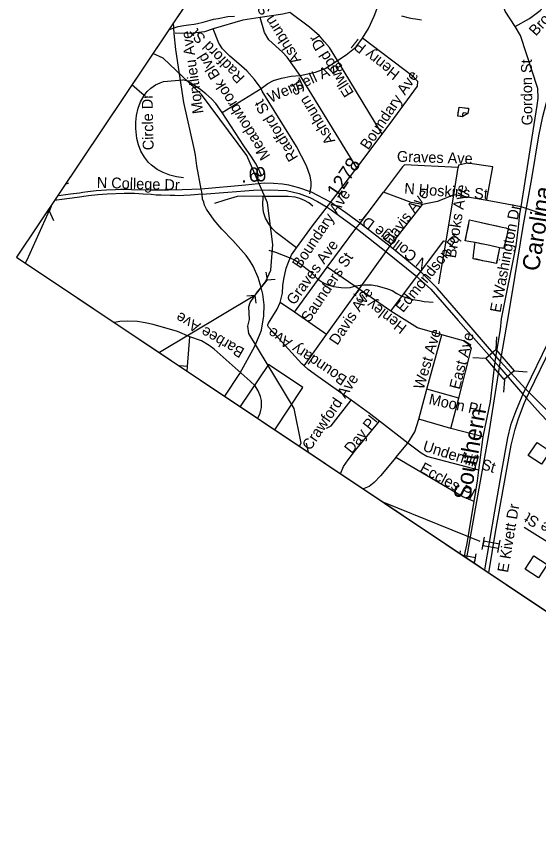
# Model space of a CAD drawing. Extents: x 1715610 to 1720914, y 798298 to 802505.
# Drawn here: x 1715610 to 1715709.6, y 799408.2 to 799566.4 of the extents above; entities that cross this region are included whole.
import ezdxf

# ---------------------------------------------------------------- set-up
doc = ezdxf.new("R2010")
doc.units = 0
doc.layers.add('Default', color=7, linetype='Continuous')
doc.layers.add('Prop DSN Text', color=7, linetype='Continuous')

msp = doc.modelspace()

# ---------------------------------------------------------------- linework, layer by layer
at = {"layer": 'Default'}
for p, q in [((1715825.88, 799842.99), (1715610.03, 799520.5)), ((1715825.88, 799842.99), (1715610.03, 799520.5)), ((1715679.77, 799543.94), (1715671.24, 799558)), ((1715674.94, 799537.52), (1715664.11, 799555.19)), ((1715649.23, 799548.1), (1715656.69, 799552.66)), ((1715674.94, 799537.52), (1715679.77, 799543.94)), ((1715669.54, 799530.39), (1715674.94, 799537.52)), ((1715693.41, 799532.38), (1715694.26, 799537.57)), ((1715619.91, 799534.58), (1715619.28, 799534.32)), ((1715675.37, 799526.71), (1715680, 799532.86)), ((1715691.98, 799523.51), (1715693.41, 799532.38)), ((1715699.76, 799531.32), (1715693.41, 799532.38)), ((1715616.28, 799529.27), (1715616.8, 799530.61)), ((1715681.11, 799522.4), (1715687.43, 799530.53)), ((1715706.25, 799530.08), (1715699.76, 799531.32)), ((1715615.76, 799529.06), (1715616.28, 799529.27)), ((1715617.16, 799527.43), (1715616.28, 799529.27)), ((1715669.3, 799518.55), (1715674.71, 799525.96)), ((1715674.71, 799525.96), (1715675.37, 799526.71)), ((1715690.56, 799515.41), (1715691.98, 799523.51)), ((1715675.35, 799514.34), (1715680.52, 799521.57)), ((1715680.52, 799521.57), (1715681.11, 799522.4)), ((1715610.03, 799520.5), (1715972.32, 799278.02)), ((1715610.03, 799520.5), (1715972.32, 799278.02)), ((1715663.02, 799509.94), (1715669.3, 799518.55)), ((1715675.35, 799514.34), (1715669.3, 799518.55)), ((1715657.59, 799517.6), (1715657.8, 799516.08)), ((1715659.34, 799516.21), (1715657.8, 799516.08)), ((1715681.41, 799510.18), (1715686.34, 799516.72)), ((1715686.34, 799516.72), (1715686.89, 799517.45)), ((1715655.51, 799513.22), (1715657.8, 799516.08)), ((1715653.97, 799513.09), (1715655.51, 799513.22)), ((1715655.72, 799511.69), (1715655.51, 799513.22)), ((1715669.14, 799505.69), (1715675.35, 799514.34)), ((1715681.41, 799510.18), (1715675.35, 799514.34)), ((1715655.17, 799512.96), (1715637.31, 799502.25)), ((1715663.02, 799509.94), (1715660.33, 799511.83)), ((1715669.14, 799505.69), (1715663.02, 799509.94)), ((1715642.65, 799499.58), (1715643.1, 799505.24)), ((1715664.87, 799499.74), (1715669.14, 799505.69)), ((1715688.3, 799495.29), (1715691.12, 799505.63)), ((1715701.58, 799505.27), (1715701.41, 799502.82)), ((1715697.05, 799501.33), (1715699.51, 799501.16)), ((1715701.34, 799500.56), (1715701.53, 799501.73)), ((1715642.65, 799499.58), (1715641.11, 799499.7)), ((1715704.94, 799498.74), (1715707.4, 799498.57)), ((1715703.08, 799497.13), (1715702.91, 799494.67)), ((1715686.73, 799489.53), (1715688.3, 799495.29)), ((1715694.36, 799493.58), (1715688.3, 799495.29)), ((1715692.88, 799487.76), (1715694.36, 799493.58)), ((1715652.69, 799491.95), (1715659.29, 799487.53)), ((1715692.88, 799487.76), (1715686.73, 799489.53)), ((1715684.67, 799484.98), (1715679.23, 799489.19)), ((1715699.01, 799486.16), (1715692.88, 799487.76)), ((1715698.23, 799479.78), (1715699.01, 799486.16)), ((1715682.37, 799482.24), (1715684.67, 799484.98)), ((1715698.43, 799466.16), (1715680.11, 799473.6)), ((1715716.53, 799462.76), (1715706.87, 799468.84)), ((1715698.84, 799464.66), (1715699.28, 799467.02)), ((1715701.82, 799464.1), (1715702.26, 799466.46)), ((1715694.64, 799463.87), (1715694.73, 799464.38)), ((1715695.23, 799463.48), (1715696.91, 799462.35)), ((1715697.38, 799462.04), (1715697.72, 799463.83))]:
    msp.add_line(p, q, dxfattribs=at)
for points in [[(1715675.99, 799562.27), (1715677.14, 799564.16), (1715678.24, 799566.46), (1715678.75, 799567.81), (1715680.1, 799572.11), (1715690.96, 799586.76), (1715694.6, 799591.45)], [(1715733.84, 799587.8), (1715729.32, 799582.48), (1715721.94, 799570.86), (1715717.48, 799562.96), (1715715.52, 799559.19), (1715714.52, 799556.87), (1715713.46, 799552.5), (1715713.22, 799550.57), (1715713.19, 799548.01), (1715714.27, 799537.69), (1715715.14, 799530.33), (1715715.35, 799527.47), (1715715.67, 799525.51), (1715715.93, 799521.37), (1715715.92, 799518.22), (1715715.57, 799515.43), (1715714.81, 799512.55), (1715713.86, 799509.92), (1715711.38, 799504.12), (1715707.11, 799495.36)], [(1715707.79, 799494.65), (1715712.08, 799503.42), (1715714.29, 799508.12), (1715714.94, 799509.43), (1715715.94, 799512.15), (1715716.75, 799515.1), (1715716.87, 799516.33), (1715716.97, 799520.41), (1715716.62, 799524.27), (1715716.37, 799527.29), (1715715.69, 799533.91), (1715714.76, 799541.07), (1715714.06, 799547.26), (1715713.99, 799549.57), (1715714.18, 799551.78), (1715714.68, 799554.51), (1715715.42, 799556.88), (1715716.77, 799559.87), (1715717.47, 799561.27), (1715721.86, 799569.03), (1715723.8, 799572.16), (1715729.96, 799581.74), (1715731.53, 799584.15), (1715733.84, 799587.8)], [(1715705.11, 799564.49), (1715703.24, 799567.47), (1715702.58, 799569.36), (1715701.97, 799572.43), (1715701.61, 799575.85), (1715701.31, 799577.72), (1715700.88, 799579.57), (1715700.38, 799581.24)], [(1715705.11, 799564.49), (1715707.86, 799566.04), (1715709.89, 799567.57), (1715711.49, 799569.38), (1715713.85, 799572.49)], [(1715671.24, 799558), (1715669.69, 799560.48), (1715668.78, 799561.62), (1715667.79, 799562.71), (1715665.88, 799564.42), (1715662.13, 799567.21), (1715660.8, 799566.85), (1715656.46, 799566.23)], [(1715695.88, 799463.04), (1715697.55, 799472.42), (1715700.02, 799486.17), (1715702.12, 799499.45), (1715702.23, 799499.92), (1715702.33, 799500.54), (1715703.93, 799509.65), (1715705.09, 799516.61), (1715706.64, 799526.36), (1715708.3, 799535.52), (1715709.62, 799543.64), (1715710.39, 799547.31), (1715711.03, 799549.75), (1715712.25, 799554.12), (1715713.05, 799556.56), (1715714.04, 799559.18), (1715715.27, 799562.03), (1715716.13, 799563.82), (1715717.08, 799565.74), (1715718.15, 799567.91)], [(1715639.1, 799563.93), (1715639.2, 799563.97), (1715639.9, 799564.23), (1715640.82, 799564.5), (1715641.91, 799564.7), (1715642.8, 799564.83), (1715643.9, 799564.98), (1715644.54, 799565.07), (1715645.61, 799565.33), (1715646.98, 799565.72), (1715647.57, 799565.89), (1715648.48, 799566.06), (1715650.3, 799566.4), (1715651.59, 799566.52)], [(1715645.24, 799533.43), (1715644.44, 799537.93), (1715644.17, 799539.98), (1715643.91, 799541.22), (1715641.95, 799550.03), (1715640.43, 799560.15), (1715640.06, 799563.17), (1715639.98, 799565.25)], [(1715656.46, 799566.23), (1715653.17, 799565.72), (1715647.53, 799564.06)], [(1715664.11, 799555.19), (1715661.61, 799558.67), (1715660.74, 799559.6), (1715658.15, 799561.98), (1715657.31, 799563.4), (1715656.46, 799566.23)], [(1715683.45, 799566.57), (1715684.91, 799566.16), (1715685.56, 799566.03), (1715686.14, 799565.95), (1715687.26, 799565.82)], [(1715647.53, 799564.06), (1715645.87, 799563.52), (1715643.12, 799563.15), (1715640.28, 799563.24)], [(1715656.69, 799552.66), (1715655.41, 799554.38), (1715653.96, 799556.08), (1715652.44, 799557.38), (1715650.69, 799558.86), (1715649.33, 799560.26), (1715648.59, 799561.32), (1715647.53, 799564.06)], [(1715706.25, 799530.08), (1715709.35, 799549.45), (1715709.54, 799550.82), (1715709.44, 799552.7), (1715706.14, 799562.83), (1715705.11, 799564.49)], [(1715671.24, 799558), (1715672.87, 799559.12), (1715674.78, 799560.62), (1715675.99, 799562.27)], [(1715679.77, 799543.94), (1715682.01, 799546.94), (1715686.48, 799553.14), (1715686.56, 799554.01), (1715685.73, 799554.92), (1715675.99, 799562.27)], [(1715663.99, 799484.39), (1715664.31, 799484.95), (1715662.95, 799491.6), (1715654.31, 799505.87), (1715654.11, 799507.31), (1715654.45, 799508.58), (1715654.35, 799510.97), (1715654.56, 799511.8), (1715656.01, 799513.83), (1715656.65, 799514.66), (1715657.49, 799515.74), (1715658.5, 799518.01), (1715658.89, 799522.92), (1715657.9, 799530.83), (1715653.95, 799539.89), (1715645.28, 799551.53), (1715637.96, 799558.5), (1715636.03, 799559.34)], [(1715664.11, 799555.19), (1715667.07, 799555.78), (1715668.87, 799556.5), (1715671.24, 799558)], [(1715634.34, 799551.33), (1715634.96, 799552.11), (1715635.66, 799552.77), (1715636.55, 799553.37), (1715637.4, 799553.79), (1715638.08, 799554.02), (1715641.71, 799554.33)], [(1715649.23, 799548.1), (1715648.04, 799549.82), (1715647.21, 799550.7), (1715646.15, 799551.68), (1715644.94, 799552.61), (1715642.61, 799554.1), (1715641.71, 799554.33)], [(1715656.69, 799552.66), (1715657.95, 799553.61), (1715659.05, 799554.19), (1715660.53, 799554.68), (1715662.4, 799555.01), (1715664.11, 799555.19)], [(1715634.34, 799551.33), (1715632.04, 799553.38)], [(1715665.98, 799532.56), (1715666.21, 799533.95), (1715666.21, 799534.87), (1715666.01, 799535.94), (1715665.36, 799537.91), (1715663.41, 799541.63), (1715656.88, 799552.19), (1715656.69, 799552.66)], [(1715641.89, 799535.63), (1715640.54, 799535.8), (1715639.25, 799536.13), (1715638.02, 799536.61), (1715636.85, 799537.24), (1715635.76, 799538.01), (1715635.19, 799538.58), (1715634.4, 799539.59), (1715633.76, 799540.71), (1715633.28, 799541.9), (1715632.97, 799543.15), (1715632.76, 799545.01), (1715632.75, 799546.28), (1715632.89, 799547.54), (1715633.23, 799548.95), (1715633.69, 799550.13), (1715634.34, 799551.33)], [(1715656.88, 799536), (1715656.61, 799536.3), (1715656.26, 799537.22), (1715655.63, 799538.43), (1715654.86, 799539.64), (1715653.37, 799541.71), (1715649.23, 799548.1)], [(1715694.46, 799549.14), (1715695.05, 799549.06), (1715695.62, 799548.98), (1715695.91, 799548.95), (1715696.2, 799548.91), (1715696.2, 799548.59), (1715696.11, 799547.92), (1715695.74, 799548), (1715695.2, 799548.06), (1715695.11, 799547.7), (1715695.01, 799547.24), (1715694.75, 799547.32), (1715694.17, 799547.4), (1715694.27, 799548.01), (1715694.36, 799548.69), (1715694.46, 799549.14)], [(1715694.46, 799549.14), (1715695.05, 799549.06), (1715695.91, 799548.95), (1715696.2, 799548.91), (1715696.2, 799548.59), (1715696.11, 799547.92), (1715695.01, 799547.24), (1715694.17, 799547.4), (1715694.36, 799548.69), (1715694.46, 799549.14)], [(1715699.76, 799531.32), (1715699.75, 799531.51), (1715700.88, 799537.71), (1715696.05, 799538.4), (1715694.34, 799538.05), (1715694.26, 799537.57)], [(1715694.26, 799537.57), (1715684.01, 799538.1), (1715683.96, 799538.05), (1715683.66, 799537.72), (1715680, 799532.86)], [(1715702.33, 799500.54), (1715701.45, 799501.54), (1715695.13, 799508.88), (1715690.24, 799514.53), (1715686.93, 799517.84), (1715681.51, 799522.29), (1715675.67, 799526.85), (1715672.8, 799528.91), (1715669.92, 799530.97), (1715666.31, 799532.86), (1715663.89, 799533.7), (1715661.96, 799534.23), (1715660.74, 799534.44), (1715659.02, 799534.56), (1715657.34, 799534.59), (1715653.72, 799534.23), (1715645.24, 799533.43)], [(1715645.41, 799532.5), (1715643.18, 799532.33), (1715641.94, 799532.24), (1715641, 799532.21), (1715640.2, 799532.22), (1715639.31, 799532.25), (1715637.58, 799532.3), (1715636.64, 799532.34), (1715635.7, 799532.41), (1715634.2, 799532.53), (1715632.51, 799532.61), (1715631.41, 799532.64), (1715630.54, 799532.66), (1715627.3, 799532.48), (1715625.52, 799532.36), (1715623.77, 799532.17), (1715621.6, 799531.88), (1715618.69, 799531.51), (1715617.68, 799531.38), (1715617.29, 799531.35)], [(1715645.24, 799533.43), (1715641.63, 799533.33), (1715638.99, 799533.27), (1715635.62, 799533.28), (1715631.95, 799533.34), (1715631.4, 799533.38), (1715630.64, 799533.39), (1715629.87, 799533.39), (1715628.89, 799533.36), (1715627.18, 799533.28), (1715625.21, 799533.11), (1715623.63, 799532.93), (1715622.69, 799532.8), (1715622.03, 799532.72), (1715620.31, 799532.5), (1715619.33, 799532.36), (1715618.56, 799532.27), (1715617.87, 799532.21)], [(1715645.41, 799532.5), (1715645.34, 799532.93), (1715645.24, 799533.43)], [(1715645.41, 799532.5), (1715655.19, 799533.25), (1715658.26, 799533.31), (1715661.54, 799533.2), (1715663.9, 799532.65), (1715665.95, 799531.89), (1715667.43, 799531.11), (1715669.27, 799529.99), (1715670.06, 799529.48), (1715674.5, 799526.24), (1715675.92, 799525.1), (1715680.75, 799521.32), (1715686.05, 799517.01), (1715689.05, 799514.36), (1715694.25, 799508.38), (1715702.12, 799499.45)], [(1715649.76, 799493.91), (1715652.6, 799498.27), (1715655.46, 799503.46), (1715656.38, 799505.55), (1715656.72, 799506.53), (1715657.22, 799509.26), (1715657.28, 799511.37), (1715656.99, 799513.44), (1715656.65, 799514.66), (1715656.13, 799516.58), (1715655.13, 799518.76), (1715654.46, 799519.92), (1715653.8, 799520.76), (1715651.28, 799523.64), (1715649.18, 799525.8), (1715647.7, 799527.52), (1715646.27, 799529.64), (1715645.9, 799530.41), (1715645.74, 799530.99), (1715645.52, 799531.54), (1715645.41, 799532.5)], [(1715657.06, 799532.07), (1715653.58, 799532.1), (1715652.11, 799532.04), (1715649.75, 799531.37), (1715647.75, 799530.7)], [(1715663.45, 799522.25), (1715659.57, 799525.16), (1715658.8, 799525.93), (1715658.12, 799526.81), (1715657.53, 799527.89), (1715657.1, 799529.06), (1715656.99, 799530.49), (1715657.06, 799532.07)], [(1715666.52, 799530.23), (1715665.77, 799530.83), (1715664.95, 799531.32), (1715664.07, 799531.69), (1715663.15, 799531.93), (1715661.86, 799532.04), (1715657.06, 799532.07)], [(1715687.43, 799530.53), (1715685.29, 799530.9), (1715680, 799532.86)], [(1715693.41, 799532.38), (1715690.31, 799531.1), (1715687.43, 799530.53)], [(1715663.45, 799522.25), (1715666.49, 799526.45), (1715669.54, 799530.39)], [(1715611.72, 799519.37), (1715612.07, 799519.97), (1715616.03, 799528.89), (1715616.61, 799530.33)], [(1715701.53, 799501.73), (1715702.32, 799506.67), (1715702.53, 799508.72), (1715705.31, 799522.63), (1715705.79, 799526.19), (1715706.03, 799528.74), (1715706.25, 799530.08)], [(1715715.5, 799527.18), (1715710.88, 799528.57), (1715706.25, 799530.08)], [(1715697.49, 799523.26), (1715696.32, 799523.48), (1715695.58, 799523.62), (1715695.69, 799524.01), (1715695.93, 799525.06), (1715696.15, 799526.07), (1715696.29, 799526.82), (1715696.38, 799527.34), (1715696.39, 799527.59), (1715697.56, 799527.37), (1715698.65, 799527.11), (1715699.75, 799526.87), (1715700.7, 799526.65), (1715701.62, 799526.44), (1715702.63, 799526.23), (1715703.35, 799526.05), (1715703.79, 799525.91), (1715703.75, 799525.62), (1715703.6, 799524.94), (1715703.4, 799524.12), (1715703.24, 799523.34), (1715703.1, 799522.74), (1715702.93, 799522.12), (1715702.71, 799522.17), (1715702.13, 799522.25)], [(1715697.49, 799523.26), (1715696.32, 799523.48), (1715695.58, 799523.62), (1715696.39, 799527.59), (1715697.56, 799527.37), (1715702.63, 799526.23), (1715703.35, 799526.05), (1715703.79, 799525.91), (1715703.75, 799525.62), (1715703.6, 799524.94), (1715703.24, 799523.34), (1715703.1, 799522.74), (1715702.93, 799522.12), (1715702.13, 799522.25)], [(1715686.89, 799517.45), (1715691.5, 799523.57), (1715691.98, 799523.51)], [(1715702.13, 799522.25), (1715702.06, 799521.93), (1715701.94, 799521.28), (1715701.82, 799520.72), (1715701.72, 799520.11), (1715701.56, 799519.58), (1715701.56, 799519.26), (1715700.68, 799519.44), (1715699.73, 799519.67), (1715698.93, 799519.8), (1715698.24, 799519.95), (1715697.75, 799520.08), (1715697.4, 799520.11), (1715697.13, 799520.18), (1715697.26, 799521.52), (1715697.35, 799522.35), (1715697.44, 799523.03), (1715697.49, 799523.26)], [(1715702.13, 799522.25), (1715701.56, 799519.26), (1715697.4, 799520.11), (1715697.13, 799520.18), (1715697.26, 799521.52), (1715697.35, 799522.35), (1715697.44, 799523.03), (1715697.49, 799523.26)], [(1715697.49, 799523.26), (1715697.51, 799523.35), (1715698.55, 799523.11), (1715699.36, 799522.98), (1715700.27, 799522.78), (1715701.09, 799522.59), (1715701.65, 799522.47), (1715702.14, 799522.35), (1715702.13, 799522.25)], [(1715697.49, 799523.26), (1715697.51, 799523.35), (1715699.36, 799522.98), (1715700.27, 799522.78), (1715701.65, 799522.47), (1715702.14, 799522.35), (1715702.13, 799522.25)], [(1715658.13, 799521.79), (1715659.42, 799521.44), (1715662.36, 799520.27), (1715663.18, 799519.93), (1715664.05, 799519.28), (1715666.04, 799517.71), (1715666.68, 799517.11), (1715667.38, 799516.43), (1715667.89, 799516.03), (1715668.43, 799515.65), (1715669.37, 799515.18), (1715670.46, 799514.85), (1715671.93, 799514.69), (1715672.73, 799514.62), (1715673.68, 799514.7), (1715674.76, 799514.97), (1715675.54, 799515.12), (1715676.32, 799515.17), (1715677.03, 799515.21), (1715677.72, 799515.21), (1715678.83, 799514.98), (1715680.77, 799514.44), (1715681.68, 799514.14), (1715682.57, 799513.53), (1715683.51, 799513.05), (1715685.6, 799512.41), (1715686.87, 799512.18), (1715687.77, 799512.03), (1715689.52, 799511.89)], [(1715660.33, 799511.83), (1715660.73, 799513.63), (1715660.82, 799515.05), (1715660.99, 799516.26), (1715661.48, 799518.35), (1715661.88, 799519.51), (1715662.49, 799520.91), (1715663.45, 799522.25)], [(1715664.87, 799499.74), (1715664.44, 799500.12), (1715658.1, 799507.1), (1715657.95, 799507.35), (1715657.93, 799507.58), (1715658.07, 799507.9), (1715659.74, 799510.55), (1715660.33, 799511.83)], [(1715691.12, 799505.63), (1715686.5, 799506.99), (1715681.41, 799510.18)], [(1715643.1, 799505.24), (1715640.71, 799506.25), (1715636.05, 799507.61), (1715634.57, 799507.96), (1715633.08, 799508.16), (1715631.26, 799508.24), (1715629.75, 799508.16), (1715628.7, 799508)], [(1715652.31, 799498.85), (1715647.74, 799502.88), (1715646.79, 799503.61), (1715645.32, 799504.5), (1715643.1, 799505.24)], [(1715694.36, 799493.58), (1715696.77, 799503.09), (1715696.24, 799503.77), (1715695.3, 799504.52), (1715691.12, 799505.63)], [(1715699.01, 799486.16), (1715700.4, 799492.94), (1715701.34, 799500.56)], [(1715707.11, 799495.36), (1715702.33, 799500.54)], [(1715642.58, 799498.72), (1715642.65, 799499.58)], [(1715656.04, 799489.71), (1715656.2, 799489.98), (1715656.49, 799490.68), (1715656.64, 799491.24), (1715656.74, 799491.8), (1715656.76, 799492.56), (1715656.73, 799493.13), (1715656.56, 799493.88), (1715656.14, 799494.93), (1715655.51, 799495.89), (1715654.6, 799496.79), (1715652.31, 799498.85)], [(1715659.29, 799487.53), (1715664.66, 799495.56), (1715658.06, 799499.98), (1715652.69, 799491.95)], [(1715673.85, 799493.15), (1715667.51, 799497.68), (1715665.64, 799499.05), (1715664.87, 799499.74)], [(1715702.12, 799499.45), (1715706.62, 799494.29)], [(1715706.62, 799494.29), (1715705.96, 799492.76), (1715705.18, 799490.96), (1715704.24, 799488.37), (1715703.64, 799485.99), (1715702.44, 799479.27), (1715701.2, 799472), (1715699.3, 799460.75)], [(1715707.11, 799495.36), (1715706.81, 799494.74), (1715706.62, 799494.29)], [(1715706.62, 799494.29), (1715706.88, 799493.99), (1715707.29, 799493.53)], [(1715707.79, 799494.65), (1715707.38, 799495.08), (1715707.11, 799495.36)], [(1715707.29, 799493.53), (1715707.65, 799494.37), (1715707.79, 799494.65)], [(1715760.72, 799449.69), (1715760.58, 799449.8), (1715753.26, 799455.6), (1715746.04, 799461.08), (1715738.6, 799466.72), (1715734.62, 799469.89), (1715730.9, 799473.01), (1715728.54, 799475.23), (1715727.1, 799476.64), (1715723.6, 799480.04), (1715719.83, 799483.39), (1715716.72, 799486.21), (1715714.47, 799488.13), (1715712.62, 799489.82), (1715710.38, 799492.02), (1715707.79, 799494.65)], [(1715669.12, 799487.83), (1715670.02, 799488.25), (1715673.85, 799493.15)], [(1715679.23, 799489.19), (1715677.36, 799490.64), (1715673.85, 799493.15)], [(1715700.09, 799460.22), (1715701.37, 799467.95), (1715704.12, 799483.17), (1715704.38, 799484.59), (1715705.11, 799487.61), (1715705.76, 799489.64), (1715706.86, 799492.55), (1715707.29, 799493.53)], [(1715707.29, 799493.53), (1715709.98, 799490.54), (1715712.78, 799487.65), (1715719.02, 799482.24), (1715726.03, 799475.8), (1715727.72, 799474.21), (1715734.06, 799468.59), (1715743.7, 799461.13), (1715748.49, 799457.6), (1715753.92, 799453.3), (1715759.88, 799448.58)], [(1715684.67, 799484.98), (1715685.97, 799487.1), (1715686.73, 799489.53)], [(1715671.84, 799479.13), (1715672.39, 799480.51), (1715673.25, 799481.78), (1715674.65, 799483.64), (1715679.23, 799489.19)], [(1715665.26, 799484.94), (1715665.67, 799483.26)], [(1715698.23, 799479.78), (1715688.31, 799482.44), (1715687.17, 799483.03), (1715684.67, 799484.98)], [(1715682.37, 799482.24), (1715679.42, 799478.75), (1715678.26, 799477.46), (1715677.28, 799476.71), (1715676.33, 799476.28), (1715676.17, 799476.23)], [(1715697.29, 799473.84), (1715695.12, 799474.71), (1715682.37, 799482.24)], [(1715697.29, 799473.84), (1715697.95, 799477.76), (1715698.23, 799479.78)], [(1715695.47, 799463.31), (1715695.65, 799464.38), (1715695.88, 799465.47), (1715697.29, 799473.84)], [(1715696.91, 799462.35), (1715697.42, 799462.26), (1715697.57, 799463.04), (1715695.23, 799463.48)]]:
    msp.add_lwpolyline(points, dxfattribs=at)
for points in [[(1715701.41, 799502.82), (1715704.95, 799498.75), (1715703.05, 799497.1), (1715699.51, 799501.16)], [(1715707.61, 799482.6), (1715709.3, 799485.11), (1715711.81, 799483.43), (1715710.13, 799480.92)], [(1715702.11, 799465.67), (1715699.13, 799466.23), (1715698.98, 799465.45), (1715701.97, 799464.89)], [(1715707.04, 799460.93), (1715708.72, 799463.45), (1715711.23, 799461.76), (1715709.55, 799459.25)]]:
    msp.add_lwpolyline(points, close=True, dxfattribs=at)
at = {"layer": 'Prop DSN Text'}
msp.add_lwpolyline([(1715972.32, 799278.02), (1716250.51, 799693.66), (1715888.23, 799936.14), (1715610.03, 799520.5)], close=True, dxfattribs=at)

# ---------------------------------------------------------------- texts
at = {"layer": 'Default'}
for s, height, rotation, p in [('Brockett Ave', 2.0663, 47.7257, (1715709.07, 799562.58)), ('Ashburn St', 2.066, 122.0781, (1715664.39, 799558.11)), ('Radford St', 2.066, 134.5095, (1715653.68, 799554.88)), ('Montlieu Ave', 2.0663, 98.1362, (1715645.67, 799548)), ('Ellwood Dr', 2.066, 121.8391, (1715674.43, 799551.85)), ('Henry Pl', 2.066, 141.6587, (1715683.27, 799555.74)), ('Meadowbrook Blvd', 2.0663, 121.7735, (1715658.48, 799539.78)), ('Wendell Ave', 2.0663, 24.6555, (1715658.49, 799549.91)), ('Gordon St', 2.066, 90.6546, (1715708.44, 799545.65)), ('Boundary Ave', 2.0663, 56.2051, (1715677.11, 799540.82)), ('Ashburn St', 2.066, 121.0525, (1715670.85, 799542.69)), ('Circle Dr', 2.066, 91.2237, (1715636.18, 799540.91)), ('Radford St', 2.066, 121.3037, (1715663.82, 799539.52)), ('Graves Ave', 2.066, 358.3413, (1715682.56, 799538.7)), ('1278', 2.719, 56.2051, (1715671.25, 799531.57)), ('6', 2.72, 4.5395, (1715654.39, 799534.8)), ('9', 2.72, 8.5473, (1715655.85, 799534.82)), ('N College Dr', 2.0663, 358.2234, (1715625.3, 799533.72)), ('.', 2.72, 4.5395, (1715652.92, 799534.68)), ('N Hoskins St', 2.0663, 355.9357, (1715683.92, 799532.61)), ('Brooks Ave', 2.066, 81.0125, (1715693.79, 799520.2)), ('Carolina', 3.263, 80.9802, (1715709.64, 799517.66)), ('Boundary Ave', 2.0663, 56.2051, (1715664.15, 799518.15)), ('Davis Ave', 2.066, 53.6781, (1715681.39, 799522.58)), ('E Washington Dr', 2.0663, 79.4262, (1715702.32, 799509.79)), ('N College Dr', 2.0663, 142.8892, (1715688.8, 799519.39)), ('Edmondson Pl', 2.0663, 51.1385, (1715683.74, 799509.76)), ('Graves Ave', 2.066, 53.8833, (1715663, 799511.19)), ('Saunders St', 2.0663, 56.2051, (1715665.85, 799507.85)), ('Davis Ave', 2.066, 56.2051, (1715671.2, 799503.52)), ('Henley St', 2.066, 142.0021, (1715684.61, 799507.3)), ('Barbee Ave', 2.066, 150.0723, (1715653.67, 799502.91)), ('Boundary Ave', 2.0663, 146.2051, (1715673.24, 799497.56)), ('West Ave', 2.066, 73.5685, (1715687.66, 799495.08)), ('East Ave', 2.066, 75.6555, (1715694.54, 799495.1)), ('Crawford Ave', 2.0663, 56.2051, (1715666.04, 799483.43)), ('Moon Pl', 2.066, 347.9951, (1715688.53, 799492.43)), ('Southern', 3.263, 79.9213, (1715696.52, 799473.93)), ('Day Pl', 2.066, 51.4236, (1715673.95, 799482.83)), ('Underhill St', 2.0663, 342.5356, (1715687.37, 799483.55)), ('Eccles Pl', 2.066, 331.4871, (1715686.76, 799479.59)), ('E Kivett Dr', 2.0663, 80.4392, (1715703.75, 799460.15)), ('Price St', 2.066, 150.3876, (1715716.04, 799466.99))]:
    msp.add_text(s, height=height, rotation=rotation, dxfattribs=at).set_placement(p)

doc.saveas('drawing.dxf')
